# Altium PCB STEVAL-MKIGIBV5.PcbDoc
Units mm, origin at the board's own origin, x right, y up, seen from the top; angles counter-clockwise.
Board outline 18 x 30.93 mm, 2 copper layers (Top Layer, Bottom Layer); 12 components, 21 nets, 46 pads, 8 vias.
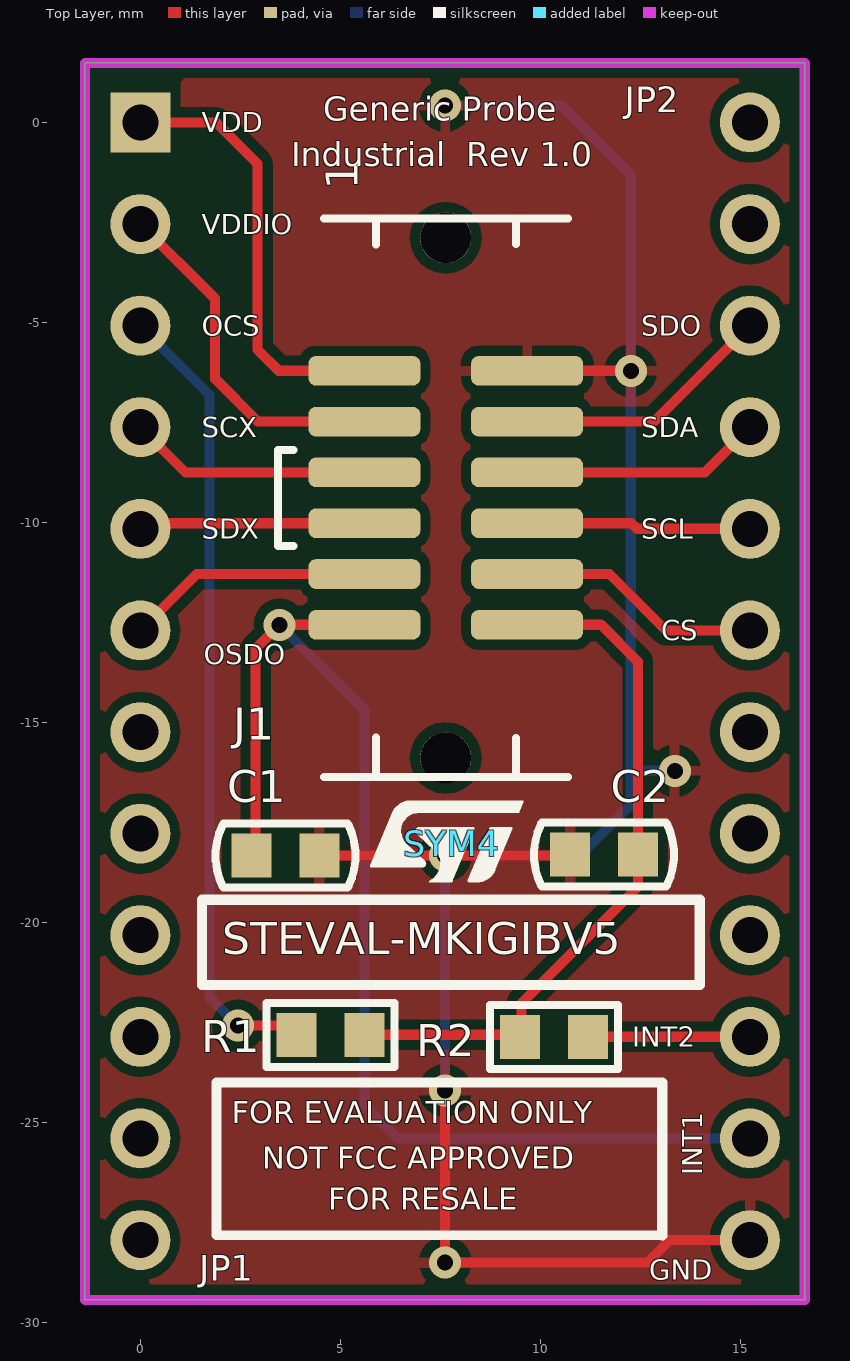
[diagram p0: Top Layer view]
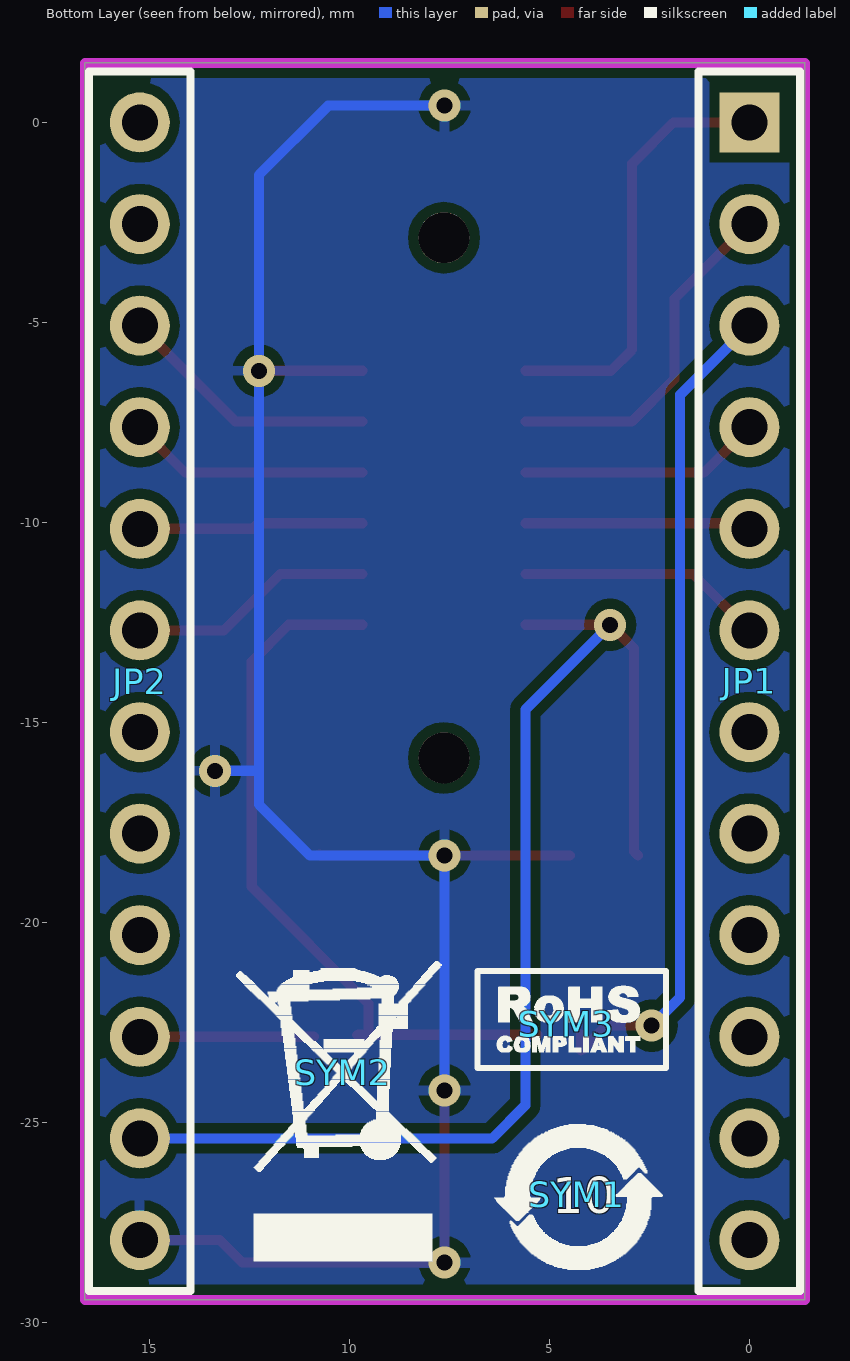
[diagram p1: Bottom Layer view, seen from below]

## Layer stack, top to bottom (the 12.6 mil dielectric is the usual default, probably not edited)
Top Layer: signal copper 0.0356
Dielectric: dielectric 0.32, FR-4, Dk 4.8
Bottom Layer: signal copper 0.0356

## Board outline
-1.387,-29.438 16.609,-29.438 16.612,-29.421 16.612,1.489 -1.387,1.489

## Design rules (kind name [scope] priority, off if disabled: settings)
Clearance [All] p1: gap=0.254
FabricationTestPointUsage TestPointUsage [All] p1: valid=0 allowmultiple=FALSE
FabricationTestpoint Testpoint [(IsPad And (OnTopLayer Or OnBottomLayer))] p1: side=3 testpointundercomponent=TRUE minsize=1.016 maxsize=2.54 preferedsize=1.524 minholesize=0 maxholesize=1.016 preferedholesize=0.813 testpointgrid=0.025 allowsidetop=TRUE allowsidebottom=TRUE usegrid=TRUE gridtolerance=0
HoleSize [All] p1: absolutevalues=TRUE maxlimit=2.54 minlimit=0.025 maxpercent=80.000 minpercent=20.000
PlaneConnect [All] p1: planeconnectstyle=Relief reliefexpansion=0.508 reliefentries=4 reliefconductorwidth=0.4 reliefairgap=0.25
PolygonConnect PolygonConnect_1 [IsVia] p1: connectstyle=Direct reliefconductorwidth=0.254 reliefentries=4 polygonreliefangle="90 Angle" airgapwidth=0.254
PolygonConnect [All] p2: connectstyle=Relief reliefconductorwidth=0.3 reliefentries=4 polygonreliefangle="90 Angle" airgapwidth=0.25
RoutingVias [All] p1: holewidth=0.3 width=0.75 viastyle="Through Hole" minholewidth=0.1 minwidth=0.5 maxholewidth=1 maxwidth=2
SolderMaskExpansion [All] p1: expansion=0.102
Width [All] p1: maxlimit=5 minlimit=0.15 preferedwidth=0.25 minimp=50.000000 maximp=50.000000 favimp=50.000000
24 further rules are at their usual default settings.

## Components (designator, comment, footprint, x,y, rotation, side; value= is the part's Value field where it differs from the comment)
C1 "CAPACITOR" SMD_C_0603_HAND 3.63,-18.33 r180 top
C2 "CAPACITOR" SMD_C_0603_HAND 11.59,-18.304 r0 top
J1 "JUMPER6x2" SMD_TRH_HDR2X06_1.27MM_BOX 7.635,-9.385 r270 top
JP1 "Header 12" HDR1X12#1 0,0 r270 bottom
JP2 "Header 12" HDR1X12#2 15.24,-27.94 r90 bottom
R1 "0R0, 62.5mW, 1%, SMD 0603" SMD_R_0603_HAND 4.75,-22.81 r180 top
R2 "0R0, 62.5mW, 1%, SMD 0603" SMD_R_0603_HAND 10.34,-22.86 r0 top
STEVAL-MKIGIBV5 "NAME BOARD" "name board" 18.134,-28.39 r90 top
SYM1 "RoHS-CH-Logo 10-4mm" "RoHS-CH-Logo 10-4mm" 4.318,-26.797 r180 bottom (schematic designator 1)
SYM2 "DUST_BIN" WASTE_5mm 10.16,-23.749 r180 bottom (schematic designator 2)
SYM3 "ROHS" Symbol_RoHS-EU-Logo-4_5mm 4.58,-22.53 r180 bottom
SYM4 "ST-LOGO" STLOGO-4mm 7.79,-18.02 r0 top (schematic designator 4)

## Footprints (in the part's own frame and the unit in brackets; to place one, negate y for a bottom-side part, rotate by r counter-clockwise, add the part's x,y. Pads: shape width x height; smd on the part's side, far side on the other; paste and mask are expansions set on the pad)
HDR1X12#1 [mm]
  rect 1.5x1.5 hole 0.9: 1(0,0)
  round 1.5 hole 0.9: 2(2.54,0) 3(5.08,0) 4(7.62,0) 5(10.16,0) 6(12.7,0) 7(15.24,0) 8(17.78,0) 9(20.32,0) 10(22.86,0) 11(25.4,0) 12(27.94,0)
  silkscreen extent -1.27,-1.27 29.21,1.27
HDR1X12#2 [mm]
  round 1.5 hole 0.9: 13(0,0) 14(2.54,0) 15(5.08,0) 16(7.62,0) 17(10.16,0) 18(12.7,0) 19(15.24,0) 20(17.78,0) 21(20.32,0) 22(22.86,0) 23(25.4,0) 24(27.94,0)
  silkscreen extent -1.27,-1.27 29.21,1.27
"name board" [mm]
"RoHS-CH-Logo 10-4mm" [mm]
  silkscreen extent -2.05,-1.88 2.14,1.74
SMD_C_0603_HAND [mm] "Chip Capacitors; Body 1.6 x 0.8 mm (LxW typ)"
  rect 1x1.1 smd: 1(-0.85,0) 2(0.85,0)
  silkscreen extent -1.75,-0.8 1.75,0.8, body extent -0.8,-0.4 0.8,0.4
SMD_R_0603_HAND [mm] "Chip Resistor; Body 1.6 x 0.8 mm (LxW typ)"
  rect 1x1.1 smd: 1(-0.85,0) 2(0.85,0)
  silkscreen extent -1.6,-0.8 1.6,0.8, body extent -0.8,-0.4 0.8,0.4
SMD_TRH_HDR2X06_1.27MM_BOX [mm] "Connector; Header; 2x6 Positions, 1.27mm, SMD"
  round 1.27 hole 1.27: 0(-6.502,0) 0(6.502,0)
  rrect50% 0.74x2.8 smd mask+0.05: 1(-3.175,-2.035) 2(-3.175,2.035) 3(-1.905,-2.035) 4(-1.905,2.035) 5(-0.635,-2.035) 6(-0.635,2.035) 7(0.635,-2.035) 8(0.635,2.035) 9(1.905,-2.035) 10(1.905,2.035) 11(3.175,-2.035) 12(3.175,2.035)
  silkscreen extent -6.98,-4.19 6.98,3.05, body extent -7.11,-2.54 7.11,2.98, height 6
STLOGO-4mm [mm]
  silkscreen extent -2.03,-0.97 1.78,1.06
Symbol_RoHS-EU-Logo-4_5mm [mm] "Symbol_RoHS-EU-Logo-4_5mm"
  silkscreen extent -2.21,-1.11 2.5,1.31
WASTE_5mm [mm]
  silkscreen extent -2.67,-4.73 2.46,2.77

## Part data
C1 C2: library part "CAP CER 0603 330pF 50V C0G/NP0 5%", "Capacitor 330pF 0603"
J1: library part "SMD Header 2x6 pins w box, 1.27mm"
JP1 JP2: "Header, 12-Pin"
R1 R2: library part "RES 0603 0R0 1% 1/16W", "RESISTOR, 0R0, 62.5mW, 1%, 0603"
SYM2: library part SYMBOL_WASTEBIN_5MM
SYM3: library part SYMBOL_EU_RoHS_4.5mm
SYM4: library part SYMBOL_STLOGO_7mm

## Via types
v1: diameter 0.8, hole 0.4, Top Layer to Bottom Layer, tented both sides, 8 vias

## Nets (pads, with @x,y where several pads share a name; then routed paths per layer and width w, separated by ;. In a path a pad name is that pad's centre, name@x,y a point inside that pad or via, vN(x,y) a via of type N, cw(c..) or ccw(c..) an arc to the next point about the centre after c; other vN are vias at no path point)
CS1: 
CS2: 
GND: 
INT1: 
INT1_2: 
INT2: 
INT3: 
INT4: 
NetR10_1: 
OCS_AUX: 
SCL: 
SCL2: 
SCX: 
SDA: 
SDA2: 
SDO1: 
SDO2: 
SDO_AUX: 
SDX: 
VDD: 
VDDIO: 
pads on no net: C1.1 C1.2 C2.1 C2.2 J1.0 J1.1 J1.2 J1.3 J1.4 J1.5 J1.6 J1.7 J1.8 J1.9 J1.10 J1.11 J1.12 JP1.1 JP1.2 JP1.3 JP1.4 JP1.5 JP1.6 JP1.7 JP1.8 JP1.9 JP1.10 JP1.11 JP1.12 JP2.13 JP2.14 JP2.15 JP2.16 JP2.17 JP2.18 JP2.19 JP2.20 JP2.21 JP2.22 JP2.23 JP2.24 R1.1 R1.2 R2.1 R2.2
copper on no net: | length 190.9
  Top Layer w0.254: 0,-12.7 1.41,-11.29 5.6,-11.29 ; 0,-7.62 1.13,-8.75 5.6,-8.75 ; 0,-2.54 1.87,-4.41 1.87,-6.41 2.94,-7.48 5.6,-7.48 ; 0,0 1.9,0 2.93,-1.03 2.93,-5.68 3.46,-6.21 5.6,-6.21 ; 0.14,-10.02 5.6,-10.02 ; v1(2.44,-22.58) 3.58,-22.58 4.205,-23.205 4.205,-22.81 ; 2.78,-18.33 2.88,-18.23 2.88,-13.16 v1(3.48,-12.56) 5.6,-12.56 ; 4.48,-18.33 v1(7.62,-18.33) 10.714,-18.33 10.74,-18.304 ; 5.295,-22.81 9.775,-22.81 9.795,-22.83 9.81,-22.815 ; v1(7.62,-24.2) v1(7.62,-28.5) 12.68,-28.5 13.24,-27.94 15.24,-27.94 ; 9.525,-22.885 9.525,-22.026 12.44,-19.111 12.44,-18.304 12.44,-13.48 11.52,-12.56 9.67,-12.56 ; 9.67,-11.29 11.73,-11.29 13.14,-12.7 15.24,-12.7 ; 9.67,-10.02 12.28,-10.02 12.42,-10.16 15.24,-10.16 ; 9.67,-8.75 14.11,-8.75 15.24,-7.62 ; 9.67,-7.48 12.84,-7.48 15.24,-5.08 ; 9.67,-6.21 v1(12.26,-6.21) ; 10.885,-22.86 15.24,-22.86 15.06,-22.68
  Bottom Layer w0.254: 0,-5.08 1.73,-6.81 1.73,-21.87 v1(2.44,-22.58) ; v1(3.48,-12.56) 5.6,-14.68 5.6,-24.57 6.43,-25.4 15.24,-25.4 ; v1(7.62,-24.2) v1(7.62,-18.33) 10.984,-18.33 12.26,-17.054 12.26,-16.21 ; v1(7.62,0.42) 10.53,0.42 12.26,-1.31 12.26,-16.21 ; v1(13.36,-16.21) 12.26,-16.21

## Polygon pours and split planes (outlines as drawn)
no net on Bottom Layer "Signal Layer 1-No Net" (solid, remove dead copper, pour order 2): -1.651,2.159 17.018,2.159 17.145,2.032 17.272,1.905 17.272,-30.48 -1.905,-30.48 -2.159,-30.226
no net on Top Layer "Signal Layer 1-No Net" (solid, remove dead copper, pour order 0): -2.54,2.667 -2.286,2.413 17.526,2.413 17.526,-29.464 16.129,-30.861 -2.54,-30.861

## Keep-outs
Keep-Out Layer:
  lines w0.254: 16.609,-29.438 -1.387,-29.438 -1.387,1.489 16.612,1.489 16.612,-29.421

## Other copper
Top Layer:
  pour cut-out: 3.146,-22.006 3.15,-22.01 6.354,-22.006 6.354,-23.614 3.146,-23.614
  pour cut-out: 8.736,-22.056 8.74,-22.06 11.944,-22.056 11.944,-23.664 8.736,-23.664
  pour cut-out: 10.95,-17.503 13.194,-17.5 13.194,-19.108 10.95,-19.108
  pour cut-out: 4.27,-19.131 2.026,-19.134 2.026,-17.526 4.27,-17.526

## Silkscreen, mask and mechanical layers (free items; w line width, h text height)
Top Overlay:
  lines w0.254: 13.046,-24.021 13.046,-27.831 1.9,-27.817 1.9,-24 13.046,-24 ; 1.537,-21.563 13.983,-21.563 13.983,-19.433 1.537,-19.433 1.537,-21.563
  text "Generic Probe" at 4.57,0.04 h0.6
  text "VDD" at 1.53,-0.25 h0.5
  text "Industrial  Rev 1.0" at 3.767,-1.09 h0.6
  text "VDDIO" at 1.53,-2.79 h0.5
  text "OCS" at 1.53,-5.33 h0.5
  text "SDO" at 12.527,-5.33 h0.5
  text "SCX" at 1.53,-7.87 h0.5
  text "SDA" at 12.527,-7.87 h0.5
  text "SDX" at 1.53,-10.41 h0.5
  text "SCL" at 12.527,-10.41 h0.5
  text "CS" at 13.027,-12.95 h0.5
  text "OSDO" at 1.58,-13.55 h0.5
  text "INT2" at 12.301,-23.11 h0.5
  text "FOR EVALUATION ONLY" at 2.286,-25.019 h0.56
  text "NOT FCC APPROVED" at 3.048,-26.162 h0.56
  text "INT1" at 14.05,-26.32 h0.5 r90
  text "FOR RESALE" at 4.699,-27.178 h0.56
  text "GND" at 12.717,-28.93 h0.5
Mechanical 4:
  lines w0.254: 16.604,1.491 -1.384,1.491 -1.376,-29.441 16.612,-29.436 16.612,1.489
Mechanical 12:
  lines w0.127: -130.812,-68.369 -125.732,-68.369 ; -130.812,-20.109 -125.732,-20.109 ; -130.812,28.151 -125.732,28.151 ; -57.787,-116.629 -57.787,-111.549 ; -57.787,71.331 -57.787,76.411 ; 15.238,-116.629 15.238,-111.549 ; 15.238,71.331 15.238,76.411 ; 41.925,-103.938 156.225,-103.938 ; 41.925,-96.318 156.225,-96.318 ; 41.925,-88.698 80.025,-88.698 ; 80.025,-103.856 80.025,-96.318 80.025,-81.078 ; 88.263,-116.629 88.263,-111.549 ; 88.263,71.331 88.263,76.411 ; 133.365,-111.558 133.365,-96.318 ; 156.208,-68.369 161.288,-68.369 ; 156.208,-20.109 161.288,-20.109 ; 156.208,28.151 161.288,28.151 ; 41.925,-111.558 6.365,-111.558 6.365,-81.078 41.925,-81.078 ; 41.925,-111.558 156.225,-111.558 156.225,-81.078 80.025,-81.078 ; 41.925,-111.558 41.925,-81.078 ; 41.925,-81.078 80.025,-81.078 ; -130.812,-116.629 -130.812,76.411 161.288,76.411 161.288,-116.629 -130.812,-116.629 ; -125.732,-111.549 -125.732,71.331 156.208,71.331 156.208,-111.549 -125.732,-111.549
  text "1" at -94.566,72.982 h1.78
  text "2" at -21.922,72.982 h1.78
  text "3" at 51.23,72.982 h1.78
  text "4" at 124.128,72.982 h1.78
  text "A" at -128.907,49.969 h1.78
  text "A" at 158.113,49.969 h1.78
  text "B" at -128.907,1.912 h1.78
  text "B" at 158.113,1.912 h1.78
  text "C" at -128.907,-46.602 h1.78
  text "C" at 158.113,-46.602 h1.78
  text "ENGINEER:" at 43.195,-83.618 h1.14
  text "TITLE:" at 81.295,-83.618 h1.14
  text "STEVAL-MKIGIBV5" at 91.658,-89.212 h1.78
  text "PCB DESIGNER:" at 43.195,-91.111 h1.14
  text "D" at -128.907,-94.608 h1.78
  text "D" at 158.113,-94.608 h1.78
  text "s" at 13.275,-96.55 h15
  text "DATE:" at 43.195,-98.858 h1.14
  text "PART NO.:" at 81.295,-98.858 h1.14
  text "REV:" at 134.635,-98.858 h1.14
  text ".Pcb_File_Name_No_Path" at 95.595,-100.972 h1.78
  text "1.0" at 143.84,-101.408 h1.78
  text "STMicroelectronics" at 10.379,-101.55 h1.78
  text "09.07.2020" at 44.465,-101.906 h1.78
  text "Via Tolomeo 1" at 10.379,-104.09 h1.78
  text "FILE NAME:" at 43.195,-106.478 h1.14
  text "DWG NO:" at 81.295,-106.478 h1.14
  text "SCALE:" at 134.635,-106.478 h1.14
  text "20010 Cornaredo (MI)" at 10.379,-106.63 h1.78
  text "Italy" at 10.379,-109.17 h1.78
  text "STEVAL-MKIGIBV5.PcbDoc" at 44.465,-109.526 h1.78
  text "1" at -94.566,-114.978 h1.78
  text "2" at -21.922,-114.978 h1.78
  text "3" at 51.23,-114.978 h1.78
  text "4" at 124.128,-114.978 h1.78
